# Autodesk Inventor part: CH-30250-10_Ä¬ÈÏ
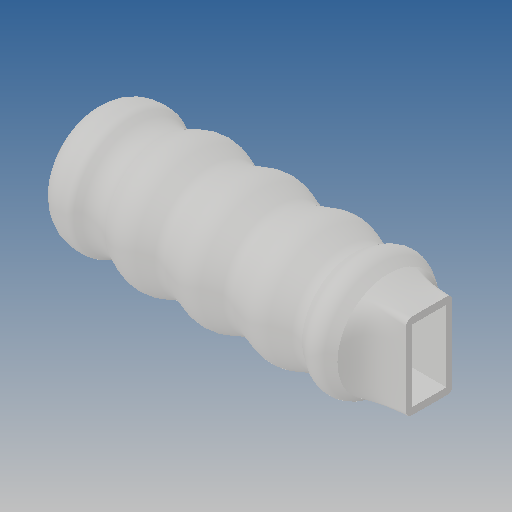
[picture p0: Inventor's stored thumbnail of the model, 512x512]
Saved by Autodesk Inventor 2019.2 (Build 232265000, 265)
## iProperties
Created: 2010-06
Part Number: CH-30250-10_Ä¬ÈÏ
Material: Ogólny
Document SubType Name: Modeling
Designer: CADENGINEERING4
Density: 1 g/cm^3
Appearance: Domyślna
Author: CADENGINEERING4
Revision Number: ÈÎºÎ
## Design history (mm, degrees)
feature "NONE"
node "Bryła1"
